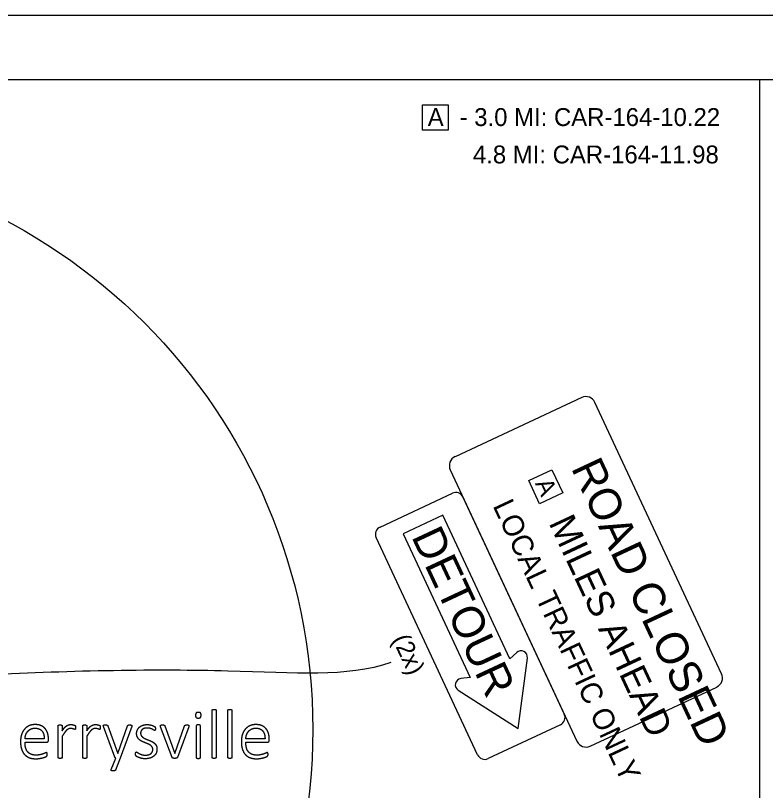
# Model space of a CAD drawing. Extents: x -740 to 1519, y 0 to 440.
# Drawn here: x 233.4 to 350.9, y 318.7 to 440 of the extents above; entities that cross this region are included whole.
import ezdxf

# ---------------------------------------------------------------- set-up
doc = ezdxf.new("R2010")
doc.units = 0
for name, color, linetype in [('Default', 7, 'Continuous'), ('GM_X_Minor_Lake', 7, 'Continuous'), ('GM_X_Minor_Lake_Text', 7, 'Continuous'), ('GM_X_Minor_River', 7, 'Continuous'), ('GM_X_Section', 7, 'Continuous'), ('GM_X_State_Location', 7, 'Continuous'), ('SH_Border', 7, 'Continuous'), ('SH_Cut_Line', 7, 'Continuous'), ('SH_Data', 7, 'Continuous')]:
    doc.layers.add(name, color=color, linetype=linetype)

msp = doc.modelspace()

# ---------------------------------------------------------------- linework, layer by layer
at = {"layer": 'GM_X_Minor_Lake'}
for points in [[(322.11, 380.21), (302.29, 370.95)], [(344.02, 336.98), (324.19, 379.45)], [(301.54, 368.88), (321.37, 326.4)], [(323.45, 325.65), (343.27, 334.9)]]:
    msp.add_lwpolyline(points, dxfattribs=at)
for centre, start, end in [((322.78, 378.79), 25.0285, 115.0285), ((302.95, 369.54), 115.0285, 205.0285), ((342.61, 336.32), 295.0285, 25.0285), ((322.79, 327.06), 205.0285, 295.0285)]:
    msp.add_arc(centre, 1.56, start, end, dxfattribs=at)
at = {"layer": 'GM_X_Minor_Lake_Text'}
msp.add_line((30, 430), (350, 430), dxfattribs=at)
at = {"layer": 'GM_X_Minor_River'}
for p, q in [((300.37, 361.78), (294.14, 358.87)), ((310.86, 339.31), (300.37, 361.78)), ((294.14, 358.87), (304.63, 336.41)), ((311.93, 340.31), (310.86, 339.31)), ((312.15, 328.42), (313.6, 339.44)), ((304.63, 336.41), (303.18, 336.22)), ((302.77, 334.39), (312.15, 328.42))]:
    msp.add_line(p, q, dxfattribs=at)
for points in [[(290.53, 359.94), (301.86, 365.23)], [(303.52, 364.63), (319.39, 330.65)], [(305.8, 324.3), (289.93, 358.28)], [(318.78, 328.99), (307.46, 323.7)]]:
    msp.add_lwpolyline(points, dxfattribs=at)
for centre, radius, start, end in [((302.39, 364.1), 1.25, 25.0285, 115.0285), ((291.06, 358.81), 1.25, 115.0285, 205.0285), ((312.61, 339.57), 1, 352.5176, 132.8474), ((303.31, 335.23), 1, 97.2096, 237.5393), ((318.25, 330.12), 1.25, 295.0285, 25.0285), ((306.93, 324.83), 1.25, 205.0285, 295.0285)]:
    msp.add_arc(centre, radius, start, end, dxfattribs=at)
at = {"layer": 'GM_X_Section'}
msp.add_line((350, 10), (350, 430), dxfattribs=at)
for points in [[(297.2, 426.04), (301.2, 426.04), (301.2, 422.04), (297.2, 422.04)], [(317.45, 368.91), (319.15, 365.29), (315.52, 363.59), (313.83, 367.22)]]:
    msp.add_lwpolyline(points, close=True, dxfattribs=at)
at = {"layer": 'GM_X_State_Location'}
for p, q in [((264.22, 323.87), (264.22, 331.24)), ((264.87, 331.24), (264.87, 323.87)), ((266.69, 323.87), (266.69, 331.24)), ((267.34, 331.24), (267.34, 323.87)), ((262.5, 330.49), (262.5, 330.49)), ((240.11, 323.87), (240.11, 328.82)), ((240.73, 328.82), (240.73, 328.04)), ((243.97, 323.87), (243.97, 328.82)), ((244.59, 328.82), (244.59, 328.04)), ((249.02, 323.9), (247.22, 328.72)), ((260.61, 328.83), (260.61, 328.83)), ((261.75, 328.82), (261.75, 323.87)), ((262.4, 323.87), (262.4, 328.82)), ((242.86, 328.57), (242.86, 328.57)), ((246.71, 328.57), (246.71, 328.57)), ((257.97, 323.87), (256.17, 328.69)), ((260.59, 328.69), (258.79, 323.87)), ((237.94, 326.79), (234.93, 326.79)), ((238.61, 326.6), (238.61, 326.73)), ((240.77, 327.22), (240.77, 323.87)), ((244.62, 327.22), (244.62, 323.87)), ((272.52, 326.79), (269.51, 326.79)), ((273.19, 326.6), (273.19, 326.73)), ((234.93, 326.25), (238.31, 326.25)), ((255.6, 325.19), (255.6, 325.19)), ((269.51, 326.25), (272.88, 326.25)), ((248.44, 322.01), (249.14, 323.76))]:
    msp.add_line(p, q, dxfattribs=at)
for points in [[(247.9, 328.82), (249.45, 324.5), (249.47, 324.5), (251, 328.82)], [(251.66, 328.72), (249.81, 323.76), (249.12, 321.91)], [(256.85, 328.82), (258.39, 324.5), (258.4, 324.47), (258.41, 324.5), (259.93, 328.82)]]:
    msp.add_lwpolyline(points, dxfattribs=at)
for points in [[(264.22, 331.24), (264.22, 331.28), (264.23, 331.3)], [(264.23, 331.3), (264.25, 331.33), (264.29, 331.35)], [(264.29, 331.35), (264.32, 331.37), (264.39, 331.38)], [(264.39, 331.38), (264.45, 331.39), (264.54, 331.39)], [(264.54, 331.39), (264.64, 331.39), (264.71, 331.38)], [(264.71, 331.38), (264.77, 331.37), (264.81, 331.35)], [(264.81, 331.35), (264.84, 331.33), (264.86, 331.3)], [(264.86, 331.3), (264.87, 331.28), (264.87, 331.24)], [(266.69, 331.24), (266.69, 331.28), (266.7, 331.3)], [(266.7, 331.3), (266.72, 331.33), (266.76, 331.35)], [(266.76, 331.35), (266.79, 331.37), (266.86, 331.38)], [(266.86, 331.38), (266.92, 331.39), (267.01, 331.39)], [(267.01, 331.39), (267.11, 331.39), (267.18, 331.38)], [(267.18, 331.38), (267.24, 331.37), (267.27, 331.35)], [(267.27, 331.35), (267.31, 331.33), (267.33, 331.3)], [(267.33, 331.3), (267.34, 331.28), (267.34, 331.24)], [(261.74, 330.84), (261.64, 330.75), (261.64, 330.48)], [(261.64, 330.48), (261.64, 330.22), (261.73, 330.13)], [(261.73, 330.13), (261.82, 330.04), (262.07, 330.04)], [(262.08, 330.93), (261.83, 330.93), (261.74, 330.84)], [(262.07, 330.04), (262.31, 330.04), (262.41, 330.13)], [(262.41, 330.84), (262.32, 330.93), (262.08, 330.93)], [(262.5, 330.49), (262.5, 330.75), (262.41, 330.84)], [(262.41, 330.13), (262.5, 330.22), (262.5, 330.49)], [(235.58, 328.84), (235.16, 328.66), (234.86, 328.31)], [(236.52, 329.02), (236, 329.02), (235.58, 328.84)], [(237.47, 328.84), (237.08, 329.02), (236.52, 329.02)], [(238.12, 328.34), (237.87, 328.65), (237.47, 328.84)], [(240.11, 328.82), (240.11, 328.85), (240.13, 328.88)], [(240.13, 328.88), (240.14, 328.91), (240.18, 328.93)], [(240.18, 328.93), (240.22, 328.95), (240.28, 328.96)], [(240.28, 328.96), (240.33, 328.96), (240.43, 328.96)], [(240.43, 328.96), (240.52, 328.96), (240.58, 328.96)], [(240.58, 328.96), (240.64, 328.95), (240.67, 328.93)], [(240.67, 328.93), (240.71, 328.91), (240.72, 328.88)], [(240.72, 328.88), (240.73, 328.85), (240.73, 328.82)], [(241.13, 328.54), (241.31, 328.73), (241.47, 328.84)], [(241.47, 328.84), (241.63, 328.95), (241.79, 328.99)], [(241.79, 328.99), (241.95, 329.02), (242.11, 329.02)], [(242.11, 329.02), (242.18, 329.02), (242.27, 329.02)], [(242.27, 329.02), (242.37, 329.01), (242.47, 328.99)], [(242.47, 328.99), (242.58, 328.96), (242.66, 328.93)], [(242.66, 328.93), (242.75, 328.9), (242.78, 328.88)], [(242.78, 328.88), (242.81, 328.85), (242.82, 328.83)], [(242.82, 328.83), (242.83, 328.82), (242.84, 328.79)], [(242.84, 328.79), (242.85, 328.76), (242.85, 328.7)], [(243.97, 328.82), (243.97, 328.85), (243.98, 328.88)], [(243.98, 328.88), (244, 328.91), (244.04, 328.93)], [(244.04, 328.93), (244.08, 328.95), (244.13, 328.96)], [(244.13, 328.96), (244.19, 328.96), (244.28, 328.96)], [(244.28, 328.96), (244.38, 328.96), (244.44, 328.96)], [(244.44, 328.96), (244.5, 328.95), (244.53, 328.93)], [(244.53, 328.93), (244.56, 328.91), (244.58, 328.88)], [(244.58, 328.88), (244.59, 328.85), (244.59, 328.82)], [(244.98, 328.54), (245.16, 328.73), (245.33, 328.84)], [(245.33, 328.84), (245.49, 328.95), (245.65, 328.99)], [(245.65, 328.99), (245.8, 329.02), (245.97, 329.02)], [(245.97, 329.02), (246.04, 329.02), (246.13, 329.02)], [(246.13, 329.02), (246.22, 329.01), (246.33, 328.99)], [(246.33, 328.99), (246.44, 328.96), (246.52, 328.93)], [(246.52, 328.93), (246.6, 328.9), (246.64, 328.88)], [(246.64, 328.88), (246.67, 328.85), (246.68, 328.83)], [(246.68, 328.83), (246.69, 328.82), (246.7, 328.79)], [(246.7, 328.79), (246.71, 328.76), (246.71, 328.7)], [(247.19, 328.85), (247.19, 328.89), (247.22, 328.92)], [(247.22, 328.72), (247.19, 328.8), (247.19, 328.85)], [(247.22, 328.92), (247.25, 328.95), (247.32, 328.96)], [(247.32, 328.96), (247.39, 328.96), (247.5, 328.96)], [(247.5, 328.96), (247.62, 328.96), (247.69, 328.96)], [(247.69, 328.96), (247.76, 328.95), (247.8, 328.93)], [(247.8, 328.93), (247.84, 328.91), (247.86, 328.89)], [(247.86, 328.89), (247.88, 328.86), (247.9, 328.82)], [(251, 328.82), (251.02, 328.9), (251.07, 328.92)], [(251.07, 328.92), (251.12, 328.95), (251.19, 328.96)], [(251.19, 328.96), (251.27, 328.96), (251.38, 328.96)], [(251.38, 328.96), (251.48, 328.96), (251.55, 328.95)], [(251.55, 328.95), (251.62, 328.94), (251.65, 328.91)], [(251.65, 328.91), (251.68, 328.89), (251.68, 328.84)], [(251.68, 328.84), (251.68, 328.79), (251.66, 328.72)], [(252.82, 328.59), (253.02, 328.78), (253.34, 328.9)], [(253.34, 328.9), (253.66, 329.02), (254.1, 329.02)], [(254.1, 329.02), (254.28, 329.02), (254.47, 328.99)], [(254.47, 328.99), (254.65, 328.96), (254.8, 328.91)], [(254.8, 328.91), (254.95, 328.86), (255.06, 328.81)], [(255.06, 328.81), (255.17, 328.75), (255.23, 328.71)], [(256.13, 328.83), (256.13, 328.87), (256.15, 328.9)], [(256.14, 328.8), (256.13, 328.82), (256.13, 328.83)], [(256.15, 328.76), (256.14, 328.79), (256.14, 328.8)], [(256.15, 328.9), (256.17, 328.93), (256.2, 328.94)], [(256.17, 328.69), (256.16, 328.73), (256.15, 328.76)], [(256.2, 328.94), (256.24, 328.95), (256.3, 328.96)], [(256.3, 328.96), (256.36, 328.96), (256.45, 328.96)], [(256.45, 328.96), (256.57, 328.96), (256.64, 328.96)], [(256.64, 328.96), (256.71, 328.95), (256.75, 328.93)], [(256.75, 328.93), (256.79, 328.91), (256.81, 328.89)], [(256.81, 328.89), (256.83, 328.86), (256.85, 328.82)], [(259.93, 328.82), (259.94, 328.86), (259.96, 328.89)], [(259.96, 328.89), (259.99, 328.91), (260.03, 328.93)], [(260.03, 328.93), (260.07, 328.95), (260.14, 328.96)], [(260.14, 328.96), (260.21, 328.96), (260.32, 328.96)], [(260.32, 328.96), (260.4, 328.96), (260.46, 328.96)], [(260.46, 328.96), (260.52, 328.95), (260.55, 328.94)], [(260.55, 328.94), (260.59, 328.92), (260.6, 328.89)], [(260.6, 328.73), (260.59, 328.71), (260.59, 328.69)], [(260.6, 328.89), (260.61, 328.87), (260.61, 328.83)], [(260.61, 328.8), (260.61, 328.78), (260.6, 328.76)], [(260.6, 328.76), (260.6, 328.74), (260.6, 328.73)], [(260.61, 328.83), (260.61, 328.82), (260.61, 328.8)], [(261.76, 328.88), (261.75, 328.85), (261.75, 328.82)], [(261.82, 328.93), (261.78, 328.91), (261.76, 328.88)], [(261.92, 328.96), (261.86, 328.95), (261.82, 328.93)], [(262.07, 328.96), (261.98, 328.96), (261.92, 328.96)], [(262.24, 328.96), (262.17, 328.96), (262.07, 328.96)], [(262.34, 328.93), (262.3, 328.95), (262.24, 328.96)], [(262.39, 328.88), (262.37, 328.91), (262.34, 328.93)], [(262.4, 328.82), (262.4, 328.85), (262.39, 328.88)], [(270.16, 328.84), (269.74, 328.66), (269.43, 328.31)], [(271.1, 329.02), (270.58, 329.02), (270.16, 328.84)], [(272.05, 328.84), (271.66, 329.02), (271.1, 329.02)], [(272.7, 328.34), (272.45, 328.65), (272.05, 328.84)], [(234.86, 328.31), (234.56, 327.96), (234.39, 327.47)], [(235.05, 327.42), (235.16, 327.72), (235.35, 327.95)], [(235.35, 327.95), (235.55, 328.18), (235.83, 328.32)], [(235.83, 328.32), (236.11, 328.46), (236.48, 328.46)], [(236.48, 328.46), (237.2, 328.46), (237.58, 328.02)], [(237.58, 328.02), (237.95, 327.58), (237.94, 326.79)], [(238.49, 327.61), (238.38, 328.02), (238.12, 328.34)], [(238.61, 326.73), (238.61, 327.19), (238.49, 327.61)], [(240.73, 328.04), (240.95, 328.35), (241.13, 328.54)], [(241.15, 327.78), (240.97, 327.55), (240.77, 327.22)], [(241.47, 328.15), (241.32, 328.01), (241.15, 327.78)], [(241.77, 328.35), (241.63, 328.29), (241.47, 328.15)], [(242.06, 328.42), (241.91, 328.42), (241.77, 328.35)], [(242.29, 328.39), (242.19, 328.42), (242.06, 328.42)], [(242.48, 328.34), (242.39, 328.37), (242.29, 328.39)], [(242.63, 328.29), (242.57, 328.31), (242.48, 328.34)], [(242.75, 328.26), (242.7, 328.26), (242.63, 328.29)], [(242.8, 328.28), (242.78, 328.26), (242.75, 328.26)], [(242.83, 328.34), (242.82, 328.3), (242.8, 328.28)], [(242.85, 328.43), (242.85, 328.37), (242.83, 328.34)], [(242.85, 328.7), (242.86, 328.65), (242.86, 328.57)], [(242.86, 328.57), (242.86, 328.49), (242.85, 328.43)], [(244.59, 328.04), (244.8, 328.35), (244.98, 328.54)], [(245, 327.78), (244.83, 327.55), (244.62, 327.22)], [(245.33, 328.15), (245.18, 328.01), (245, 327.78)], [(245.63, 328.35), (245.49, 328.29), (245.33, 328.15)], [(245.92, 328.42), (245.77, 328.42), (245.63, 328.35)], [(246.15, 328.39), (246.04, 328.42), (245.92, 328.42)], [(246.34, 328.34), (246.25, 328.37), (246.15, 328.39)], [(246.49, 328.29), (246.42, 328.31), (246.34, 328.34)], [(246.6, 328.26), (246.56, 328.26), (246.49, 328.29)], [(246.66, 328.28), (246.64, 328.26), (246.6, 328.26)], [(246.69, 328.34), (246.68, 328.3), (246.66, 328.28)], [(246.71, 328.43), (246.7, 328.37), (246.69, 328.34)], [(246.71, 328.7), (246.71, 328.65), (246.71, 328.57)], [(246.71, 328.57), (246.71, 328.49), (246.71, 328.43)], [(252.41, 327.63), (252.41, 327.89), (252.51, 328.14)], [(252.52, 327.08), (252.41, 327.31), (252.41, 327.63)], [(252.51, 328.14), (252.61, 328.39), (252.82, 328.59)], [(253.1, 327.99), (253.04, 327.84), (253.04, 327.67)], [(253.04, 327.67), (253.04, 327.43), (253.15, 327.26)], [(253.29, 328.25), (253.17, 328.14), (253.1, 327.99)], [(253.61, 328.42), (253.42, 328.36), (253.29, 328.25)], [(254.06, 328.48), (253.81, 328.48), (253.61, 328.42)], [(254.52, 328.42), (254.32, 328.48), (254.06, 328.48)], [(254.86, 328.29), (254.72, 328.36), (254.52, 328.42)], [(255.09, 328.16), (255, 328.22), (254.86, 328.29)], [(255.22, 328.1), (255.18, 328.1), (255.09, 328.16)], [(255.28, 328.11), (255.25, 328.1), (255.22, 328.1)], [(255.23, 328.71), (255.28, 328.66), (255.3, 328.63)], [(255.32, 328.17), (255.3, 328.13), (255.28, 328.11)], [(255.3, 328.63), (255.32, 328.6), (255.33, 328.57)], [(255.34, 328.26), (255.33, 328.21), (255.32, 328.17)], [(255.33, 328.57), (255.34, 328.54), (255.34, 328.49)], [(255.34, 328.49), (255.35, 328.44), (255.35, 328.38)], [(255.35, 328.38), (255.35, 328.31), (255.34, 328.26)], [(269.43, 328.31), (269.13, 327.96), (268.97, 327.47)], [(269.63, 327.42), (269.74, 327.72), (269.93, 327.95)], [(269.93, 327.95), (270.12, 328.18), (270.41, 328.32)], [(270.41, 328.32), (270.69, 328.46), (271.06, 328.46)], [(271.06, 328.46), (271.78, 328.46), (272.16, 328.02)], [(272.16, 328.02), (272.53, 327.58), (272.52, 326.79)], [(273.07, 327.61), (272.96, 328.02), (272.7, 328.34)], [(273.19, 326.73), (273.19, 327.19), (273.07, 327.61)], [(234.39, 327.47), (234.23, 326.97), (234.23, 326.34)], [(234.23, 326.34), (234.23, 325.68), (234.39, 325.19)], [(234.93, 326.79), (234.95, 327.12), (235.05, 327.42)], [(238.31, 326.25), (238.4, 326.25), (238.51, 326.33)], [(238.51, 326.33), (238.61, 326.4), (238.61, 326.6)], [(252.81, 326.69), (252.63, 326.85), (252.52, 327.08)], [(253.21, 326.41), (252.99, 326.52), (252.81, 326.69)], [(253.15, 327.26), (253.26, 327.1), (253.44, 326.98)], [(253.68, 326.2), (253.44, 326.3), (253.21, 326.41)], [(253.44, 326.98), (253.62, 326.86), (253.85, 326.77)], [(253.85, 326.77), (254.08, 326.67), (254.32, 326.58)], [(254.32, 326.58), (254.56, 326.49), (254.79, 326.37)], [(254.79, 326.37), (255.02, 326.26), (255.2, 326.1)], [(268.97, 327.47), (268.81, 326.97), (268.81, 326.34)], [(268.81, 326.34), (268.81, 325.68), (268.97, 325.19)], [(269.51, 326.79), (269.53, 327.12), (269.63, 327.42)], [(272.88, 326.25), (272.98, 326.25), (273.09, 326.33)], [(273.09, 326.33), (273.19, 326.4), (273.19, 326.6)], [(234.39, 325.19), (234.54, 324.69), (234.85, 324.35)], [(235.02, 325.42), (234.93, 325.79), (234.93, 326.25)], [(235.32, 324.79), (235.11, 325.05), (235.02, 325.42)], [(254.14, 326.01), (253.92, 326.1), (253.68, 326.2)], [(254.55, 325.81), (254.37, 325.92), (254.14, 326.01)], [(254.83, 325.53), (254.72, 325.69), (254.55, 325.81)], [(254.94, 325.14), (254.94, 325.37), (254.83, 325.53)], [(254.86, 324.74), (254.94, 324.91), (254.94, 325.14)], [(255.2, 326.1), (255.38, 325.95), (255.49, 325.72)], [(255.6, 325.19), (255.6, 324.84), (255.47, 324.55)], [(255.49, 325.72), (255.6, 325.5), (255.6, 325.19)], [(268.97, 325.19), (269.12, 324.69), (269.42, 324.35)], [(269.6, 325.42), (269.51, 325.79), (269.51, 326.25)], [(269.9, 324.79), (269.69, 325.05), (269.6, 325.42)], [(234.85, 324.35), (235.15, 324.02), (235.59, 323.84)], [(235.86, 324.38), (235.53, 324.52), (235.32, 324.79)], [(236.68, 324.24), (236.2, 324.24), (235.86, 324.38)], [(237.3, 324.3), (237.03, 324.24), (236.68, 324.24)], [(237.77, 324.43), (237.57, 324.36), (237.3, 324.3)], [(238.1, 324.57), (237.97, 324.51), (237.77, 324.43)], [(237.79, 323.85), (238.02, 323.92), (238.16, 323.98)], [(238.28, 324.63), (238.23, 324.63), (238.1, 324.57)], [(238.16, 323.98), (238.3, 324.05), (238.33, 324.08)], [(238.34, 324.61), (238.31, 324.63), (238.28, 324.63)], [(238.33, 324.08), (238.36, 324.11), (238.37, 324.13)], [(238.39, 324.56), (238.37, 324.59), (238.34, 324.61)], [(238.37, 324.13), (238.39, 324.16), (238.4, 324.19)], [(238.41, 324.47), (238.4, 324.52), (238.39, 324.56)], [(238.4, 324.19), (238.41, 324.22), (238.41, 324.26)], [(238.42, 324.33), (238.42, 324.41), (238.41, 324.47)], [(238.41, 324.26), (238.42, 324.29), (238.42, 324.33)], [(240.13, 323.81), (240.11, 323.84), (240.11, 323.87)], [(240.77, 323.87), (240.77, 323.84), (240.75, 323.81)], [(243.98, 323.81), (243.97, 323.84), (243.97, 323.87)], [(244.62, 323.87), (244.62, 323.84), (244.61, 323.81)], [(249.06, 323.82), (249.03, 323.86), (249.02, 323.9)], [(252.24, 324.43), (252.24, 324.5), (252.25, 324.56)], [(252.27, 324.21), (252.24, 324.29), (252.24, 324.43)], [(252.25, 324.56), (252.26, 324.61), (252.28, 324.65)], [(252.35, 324.08), (252.29, 324.13), (252.27, 324.21)], [(252.28, 324.65), (252.29, 324.69), (252.32, 324.71)], [(252.32, 324.71), (252.35, 324.73), (252.38, 324.73)], [(252.54, 323.95), (252.41, 324.02), (252.35, 324.08)], [(252.38, 324.73), (252.44, 324.73), (252.56, 324.65)], [(252.86, 323.82), (252.67, 323.88), (252.54, 323.95)], [(252.56, 324.65), (252.67, 324.57), (252.84, 324.48)], [(252.84, 324.48), (253.02, 324.39), (253.25, 324.31)], [(253.25, 324.31), (253.49, 324.24), (253.8, 324.24)], [(253.8, 324.24), (254.05, 324.24), (254.26, 324.29)], [(254.26, 324.29), (254.47, 324.35), (254.62, 324.46)], [(255.09, 324.08), (254.85, 323.88), (254.51, 323.77)], [(254.62, 324.46), (254.77, 324.57), (254.86, 324.74)], [(255.47, 324.55), (255.33, 324.27), (255.09, 324.08)], [(258.02, 323.81), (257.98, 323.83), (257.97, 323.87)], [(258.79, 323.87), (258.78, 323.83), (258.74, 323.8)], [(261.75, 323.87), (261.75, 323.84), (261.76, 323.81)], [(262.39, 323.81), (262.4, 323.84), (262.4, 323.87)], [(264.23, 323.81), (264.22, 323.84), (264.22, 323.87)], [(264.87, 323.87), (264.87, 323.84), (264.86, 323.81)], [(266.7, 323.81), (266.69, 323.84), (266.69, 323.87)], [(267.34, 323.87), (267.34, 323.84), (267.33, 323.81)], [(269.42, 324.35), (269.72, 324.02), (270.17, 323.84)], [(270.44, 324.38), (270.11, 324.52), (269.9, 324.79)], [(271.26, 324.24), (270.77, 324.24), (270.44, 324.38)], [(271.88, 324.3), (271.6, 324.24), (271.26, 324.24)], [(272.35, 324.43), (272.15, 324.36), (271.88, 324.3)], [(272.68, 324.57), (272.55, 324.51), (272.35, 324.43)], [(272.37, 323.85), (272.6, 323.92), (272.74, 323.98)], [(272.86, 324.63), (272.81, 324.63), (272.68, 324.57)], [(272.74, 323.98), (272.88, 324.05), (272.91, 324.08)], [(272.92, 324.61), (272.89, 324.63), (272.86, 324.63)], [(272.91, 324.08), (272.94, 324.11), (272.95, 324.13)], [(272.96, 324.56), (272.95, 324.59), (272.92, 324.61)], [(272.95, 324.13), (272.97, 324.16), (272.98, 324.19)], [(272.99, 324.47), (272.98, 324.52), (272.96, 324.56)], [(272.98, 324.19), (272.99, 324.22), (272.99, 324.26)], [(273, 324.33), (273, 324.41), (272.99, 324.47)], [(272.99, 324.26), (273, 324.29), (273, 324.33)], [(235.59, 323.84), (236.03, 323.67), (236.6, 323.67)], [(236.6, 323.67), (236.95, 323.67), (237.26, 323.73)], [(237.26, 323.73), (237.56, 323.78), (237.79, 323.85)], [(240.18, 323.77), (240.14, 323.79), (240.13, 323.81)], [(240.28, 323.74), (240.22, 323.75), (240.18, 323.77)], [(240.44, 323.73), (240.34, 323.73), (240.28, 323.74)], [(240.6, 323.74), (240.54, 323.73), (240.44, 323.73)], [(240.7, 323.77), (240.66, 323.75), (240.6, 323.74)], [(240.75, 323.81), (240.73, 323.79), (240.7, 323.77)], [(244.04, 323.77), (244, 323.79), (243.98, 323.81)], [(244.14, 323.74), (244.08, 323.75), (244.04, 323.77)], [(244.3, 323.73), (244.2, 323.73), (244.14, 323.74)], [(244.46, 323.74), (244.39, 323.73), (244.3, 323.73)], [(244.56, 323.77), (244.52, 323.75), (244.46, 323.74)], [(244.61, 323.81), (244.59, 323.79), (244.56, 323.77)], [(249.14, 323.76), (249.1, 323.78), (249.06, 323.82)], [(253.27, 323.71), (253.04, 323.75), (252.86, 323.82)], [(253.76, 323.67), (253.5, 323.67), (253.27, 323.71)], [(254.51, 323.77), (254.17, 323.67), (253.76, 323.67)], [(258.1, 323.76), (258.05, 323.78), (258.02, 323.81)], [(258.22, 323.74), (258.15, 323.75), (258.1, 323.76)], [(258.38, 323.73), (258.29, 323.73), (258.22, 323.74)], [(258.54, 323.74), (258.47, 323.73), (258.38, 323.73)], [(258.66, 323.76), (258.61, 323.74), (258.54, 323.74)], [(258.74, 323.8), (258.71, 323.77), (258.66, 323.76)], [(261.76, 323.81), (261.78, 323.79), (261.82, 323.77)], [(261.82, 323.77), (261.86, 323.75), (261.92, 323.74)], [(261.92, 323.74), (261.98, 323.73), (262.07, 323.73)], [(262.07, 323.73), (262.17, 323.73), (262.24, 323.74)], [(262.24, 323.74), (262.3, 323.75), (262.34, 323.77)], [(262.34, 323.77), (262.37, 323.79), (262.39, 323.81)], [(264.29, 323.77), (264.25, 323.79), (264.23, 323.81)], [(264.39, 323.74), (264.32, 323.75), (264.29, 323.77)], [(264.54, 323.73), (264.45, 323.73), (264.39, 323.74)], [(264.71, 323.74), (264.64, 323.73), (264.54, 323.73)], [(264.81, 323.77), (264.77, 323.75), (264.71, 323.74)], [(264.86, 323.81), (264.84, 323.79), (264.81, 323.77)], [(266.76, 323.77), (266.72, 323.79), (266.7, 323.81)], [(266.86, 323.74), (266.79, 323.75), (266.76, 323.77)], [(267.01, 323.73), (266.92, 323.73), (266.86, 323.74)], [(267.18, 323.74), (267.11, 323.73), (267.01, 323.73)], [(267.27, 323.77), (267.24, 323.75), (267.18, 323.74)], [(267.33, 323.81), (267.31, 323.79), (267.27, 323.77)], [(270.17, 323.84), (270.61, 323.67), (271.18, 323.67)], [(271.18, 323.67), (271.53, 323.67), (271.84, 323.73)], [(271.84, 323.73), (272.14, 323.78), (272.37, 323.85)], [(248.41, 321.9), (248.41, 321.94), (248.44, 322.01)], [(248.45, 321.82), (248.42, 321.85), (248.41, 321.9)], [(248.56, 321.78), (248.49, 321.79), (248.45, 321.82)], [(248.72, 321.77), (248.62, 321.77), (248.56, 321.78)], [(249, 321.81), (248.91, 321.77), (248.72, 321.77)], [(249.12, 321.91), (249.09, 321.85), (249, 321.81)]]:
    msp.add_open_spline(points, degree=2, dxfattribs=at)
at = {"layer": 'SH_Border'}
msp.add_lwpolyline([(30, 430), (670, 430), (670, 10), (30, 10)], close=True, dxfattribs=at)
at = {"layer": 'SH_Cut_Line'}
msp.add_lwpolyline([(0, 0), (680, 0), (680, 440), (0, 440)], close=True, dxfattribs=at)
at = {"layer": 'SH_Data'}
msp.add_circle((190, 328.25), 90, dxfattribs=at)
for points, degree in [([(292.24, 338.74), (285.13, 336.33), (269.67, 337.89), (228.49, 337.27), (203.65, 334.85), (190.1, 330.19)], 3), ([(301.11, 286.38), (297.47, 298.35), (284.27, 305.71), (265.34, 312.77), (224.97, 312.3), (209.77, 315.51), (196.1, 322.76)], 2)]:
    msp.add_open_spline(points, degree=degree, dxfattribs=at)

# ---------------------------------------------------------------- texts
at = {"layer": 'Default'}
msp.add_text('(2x)', height=2.8, rotation=295.0285, dxfattribs=at).set_placement((292.4, 342.38))
at = {"layer": 'GM_X_Minor_Lake'}
for s, height, p in [('ROAD CLOSED', 5, (320.39, 369.2)), ('LOCAL TRAFFIC ONLY', 3.3333, (308.13, 363.28)), ('MILES AHEAD', 4.1667, (316.9, 360.59))]:
    msp.add_text(s, height=height, rotation=295.0285, dxfattribs=at).set_placement(p)
at = {"layer": 'GM_X_Minor_River'}
msp.add_text('DETOUR', height=5, rotation=295.0285, dxfattribs=at).set_placement((295.38, 358.47))
at = {"layer": 'GM_X_Section'}
for s, p in [('A', (298, 422.7)), ('- 3.0 MI: CAR-164-10.22', (303, 422.7)), ('  4.8 MI: CAR-164-11.98', (303, 416.85))]:
    msp.add_text(s, height=2.8, dxfattribs=at).set_placement(p)
msp.add_text('A', height=2.8, rotation=295.0285, dxfattribs=at).set_placement((314.77, 366.77))

doc.saveas('drawing.dxf')
